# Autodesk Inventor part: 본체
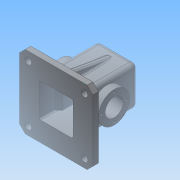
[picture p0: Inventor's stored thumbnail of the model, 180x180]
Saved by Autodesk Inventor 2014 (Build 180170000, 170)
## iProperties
Created: 2016-02
Part Number: 본체
Material: 일반
Document SubType Name: Modeling
Designer: net
Density: 1 g/cm^3
Appearance: 기본값
Author: net
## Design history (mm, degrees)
sketch "스케치1"
  geometry: L1 (0, -130)-(-130, -130); L2 (-130, -130)-(-130, 0); L3 (-130, 0)-(0, 0); L4 (0, 0)-(0, -130); 1 further point
  constraints: 8 end point, 2 parallel, 1 coincident, 1 horizontal, 1 perpendicular
  dimensions: "d0" = 130 distance of L1.start L1.end; "d1" = 130 distance of L1.end L2.end
extrude "돌출1" new body sketch "스케치1" distance "d2" = 10; taper "d3" = 0 deg
sketch "스케치2"
  geometry: L1 (130, 130)-(0, 130) reference; L2 (130, 0)-(130, 130) reference; L3 (130, 130)-(0, 130) reference; L4 (0, 130)-(0, 0) reference; L5 (0, 0)-(130, 0) reference; L6 (130, 0)-(130, 130) reference; L7 (65, 130)-(65, 0); L8 (0, 65)-(130, 65); L9 (30, 100)-(100, 100); L10 (100, 100)-(100, 30); L11 (100, 30)-(30, 30); L12 (30, 30)-(30, 100); 1 further point
  constraints: 12 end point, 4 midpoint, 2 parallel, 1 horizontal, 1 perpendicular
  dimensions: "d6" = 70 distance between parallel lines of L12 L10; "d7" = 35 distance between parallel lines of L7 L10; "d8" = 70 distance between parallel lines of L11 L9; "d9" = 35 distance between parallel lines of L8 L9
extrude "돌출2" join sketch "스케치2" distance "d10" = 100; taper "d11" = 0 deg
chamfer "모따기1" distance "d12" = 10; stored, may be unused: second distance "d13" = 2, angle "d14" = 45 deg
sketch "스케치3"
  geometry: L1 (0, 100)-(70, 100) reference; L2 (70, 0)-(70, 100) reference; L3 (0, 0)-(0, 100) reference; L4 (-20, 0)-(90, 0) reference; L5 (90, -10)-(-20, -10) reference; L6 (35, -10)-(35, 45); C1 r 27.5 at (35, 45); 1 further point
  constraints: 2 end point, 1 centre point, 1 coincident, 1 midpoint, 1 perpendicular
  dimensions: "d15" = 55 distance of L6.start L6.end; "d16" = 55 diameter of C1
extrude "돌출3" join sketch "스케치3" distance "d17" = 13; taper "d18" = 0 deg
node "작업 평면1"
sketch "스케치4"
  geometry: L1 (100, 100)-(30, 100) reference; L2 (100, 30)-(100, 100) reference; L3 (30, 30)-(100, 30) reference; L4 (30, 100)-(30, 30) reference; L5 (65, 100)-(65, 30); L6 (30, 65)-(100, 65); C1 r 20 at (65, 65); 1 further point
  constraints: 5 midpoint, 4 end point, 1 centre point
  dimensions: "d19" = 40 diameter of C1
extrude "돌출4" join sketch "스케치4" distance "d20" = 10; taper "d21" = 0 deg
feature "면 기울기1" dims angle "d22" = 10 deg
fillet "모깎기1" dims "d23" = 8
fillet "모깎기2" dims "d24" = 8
fillet "모깎기3" dims "d25" = 3
sketch "스케치5"
  geometry: 1 further point
node "작업 평면2"
sketch "스케치6"
  geometry: L1 (-3, 95)-(57, 95); L2 (57, -20)-(-3, -20); L3 (-8, 50.22)-(-8, 92) reference; L4 (62, 92)-(62, 50.22) reference; L5 (0, 100)-(54, 100) reference; L6 (-21, 17.5)-(-21, 72.5) reference; L7 (75, 17.5)-(75, 72.5) reference; L8 (-21, 45)-(75, 45); L9 (-3, -20)-(-3, 17.5); L10 (-3, 72.5)-(-3, 95); L11 (57, 17.5)-(57, -20); L12 (4, 17.5)-(10.978, 17.5); L13 (-3, 17.5)-(4, 24.5); L14 (50, 65.5)-(50, 24.5); L15 (4, 24.5)-(4, 65.5); L16 (-3, 17.5)-(4, 17.5); L17 (-3, 72.5)-(4, 65.5); L18 (27, 95)-(27, -20); L19 (57, 72.5)-(50, 65.5); L20 (50, 24.5)-(50, 65.5); L21 (57, 17.5)-(50, 24.5); L22 (57, 95)-(57, 72.5); 1 further point
  constraints: 34 end point, 7 parallel, 4 midpoint, 4 symmetric about line, 2 horizontal, 2 perpendicular, 1 point on line
  dimensions: "d29" = 5 distance between parallel lines of L1 L5; "d35" = 7 distance between parallel lines of L15 L10; "d36" = 45 deg angle of L16 L13; "d37" = 135 deg angle of L15 L17; "d39" = 115 distance between parallel lines of L2 L1; "d40" = 60 distance between parallel lines of L11 L9; "d41" = 55 distance of L11.start L19.start; "d42" = 55 distance of L9.end L10.start; "d43" = 5 distance between parallel lines of L10 L3; "d44" = 5 distance between parallel lines of L4 L22
extrude "돌출5" cut sketch "스케치6" stored distance "d45" = 60; taper "d46" = 0 deg
sketch "스케치7"
  geometry: C1 r 27.5 at (0, 0) reference; C2 r 16 at (0, 0); 1 further point
  constraints: 1 centre point, 1 coincident
  dimensions: "d47" = 32 diameter of C2
extrude "돌출6" cut sketch "스케치7" stored distance "d48" = 60; taper "d49" = 0 deg
sketch "스케치8"
  geometry: C1 r 27.5 at (0, 0) reference; C2 r 16 at (0, 0); 1 further point
  constraints: 1 centre point, 1 coincident
  dimensions: "d50" = 32 diameter of C2
extrude "돌출7" cut sketch "스케치8" stored distance "d51" = 60; taper "d52" = 0 deg
sketch "스케치9"
  geometry: L1 (0, 22.5)-(0, -22.5); C1 r 27.5 at (0, 0) reference; A1 r 22.5 centre (0, 0) between (0, 22.5) and (0, -22.5); 3 further points
  constraints: 3 coincident, 2 end point, 2 point on circle, 1 centre point, 1 midpoint, 1 vertical
  dimensions: "d53" = 45 diameter of A1
hole "구멍1" sketch "스케치9" at (0, 22.5) diameter "d54" = 4; stored, may be unused: countersink angle "d58" = 90 deg, drill point angle "d60" = 118 deg; dims "d55" = 6, "d56" = 4, "d57" = 2, "d59" = 10
feature "스레드1" dims "d61" = 8, "d62" = 0
feature "스레드2" dims "d66" = 8, "d67" = 0
sketch "스케치10"
  geometry: L1 (100, 0)-(100, -10) reference; L2 (85, 0)-(85, -10); L3 (70, 92)-(70, 0) reference; L4 (85, 0)-(168.896, 0); L5 (85, 0)-(159.352, 0); L6 (85, 0)-(70, 85.069); L7 (85, 0)-(171.382, 0); L8 (90, 0)-(-20, 0) reference; L9 (65, 72.5)-(65, 95) reference; L10 (70, 85.069)-(70, 0); L11 (85, 0)-(70, 0); 1 further point
  constraints: 14 end point, 3 horizontal, 2 point on line, 1 collinear, 1 parallel, 1 perpendicular
  dimensions: "d71" = 15 distance between parallel lines of L1 L2; "d74" = 100 deg angle of L7 L6
extrude "돌출8" join sketch "스케치10" stored distance "d76" = 10; taper "d77" = 0 deg
fillet "모깎기5" dims "d79" = 3
fillet "모깎기6" dims "d80" = 3
fillet "모깎기7" dims "d81" = 3
sketch "스케치11"
  geometry: L1 (35, -45)-(35, 47) reference; L2 (20, 65)-(-20, 65) reference; 3 further points
  constraints: 1 other
  dimensions: "d83" = 35 distance from line of L1 point (0, 35); "d84" = 30 distance from line of point (0, 35) L2
feature "엠보싱1" sketch "스케치11" dims "d6" = 70, "d7" = 35, "d8" = 70, "d9" = 35, "d85" = 0.5, "d86" = 0
sketch "스케치12"
  geometry: C1 r 20 at (0, 0) reference; C2 r 20 at (0, 0) reference; C3 r 14 at (0, 0); 1 further point
  constraints: 1 centre point, 1 coincident
  dimensions: "d87" = 28 diameter of C3
extrude "돌출9" cut sketch "스케치12" distance "d88" = 4; taper "d89" = 0 deg
sketch "스케치13"
  geometry: C1 r 14 at (0, 0) reference; C2 r 10.5 at (0, 0); 1 further point
  constraints: 1 centre point, 1 coincident
  dimensions: "d90" = 21 diameter of C2
extrude "돌출10" cut sketch "스케치13" stored distance "d91" = 4; taper "d92" = 0 deg
sketch "스케치14"
  geometry: L1 (120, 130)-(10, 130) reference; L2 (0, 120)-(0, 10) reference; L3 (10, 0)-(120, 0) reference; L4 (130, 10)-(130, 120) reference; L5 (65, 130)-(65, 0); L6 (0, 65)-(130, 65); C1 r 6 at (115, 115); C2 r 6 at (15, 115); C3 r 6 at (15, 15); C4 r 6 at (115, 15); 1 further point
  constraints: 4 centre point, 4 end point, 4 midpoint, 2 horizontal alignment, 2 vertical alignment
  dimensions: "d93" = 12 diameter of C1; "d94" = 12 diameter of C2; "d95" = 12 diameter of C3; "d96" = 12 diameter of C4; "d97" = 50 distance from line of L5 C2.centre; "d98" = 100 distance of C2.centre C1.centre; "d99" = 100 distance of C3.centre C2.centre; "d100" = 50 distance from line of L6 C2.centre
extrude "돌출11" cut sketch "스케치14" stored distance "d101" = 4; taper "d102" = 0 deg; dims "d27" = 5, "d80" = 3, "d99" = 100, "d103" = 3, "d107" = 0.5
fillet "모깎기9" dims "d103" = 3
fillet "모깎기10" dims "d104" = 3
fillet "모깎기11" dims "d105" = 0.5
fillet "모깎기12" dims "d106" = 0.5
fillet "모깎기13" dims "d107" = 0.5
fillet "모깎기14" dims "d108" = 0.5
node "솔리드1"
mirror "대칭1"
pattern_circular "원형 패턴1" dims angle "d64" = 360 deg
mirror "대칭2"
pattern_circular "원형 패턴2" dims "d69" = 360 deg
mirror "대칭3"
node "투영된 루프1"
node "투영된 루프2"
other parameters: "d28" = 5, "d31" = 55, "d32" = 27.5, "d38" = 7
